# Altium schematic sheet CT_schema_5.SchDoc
size 235 x 258 mm
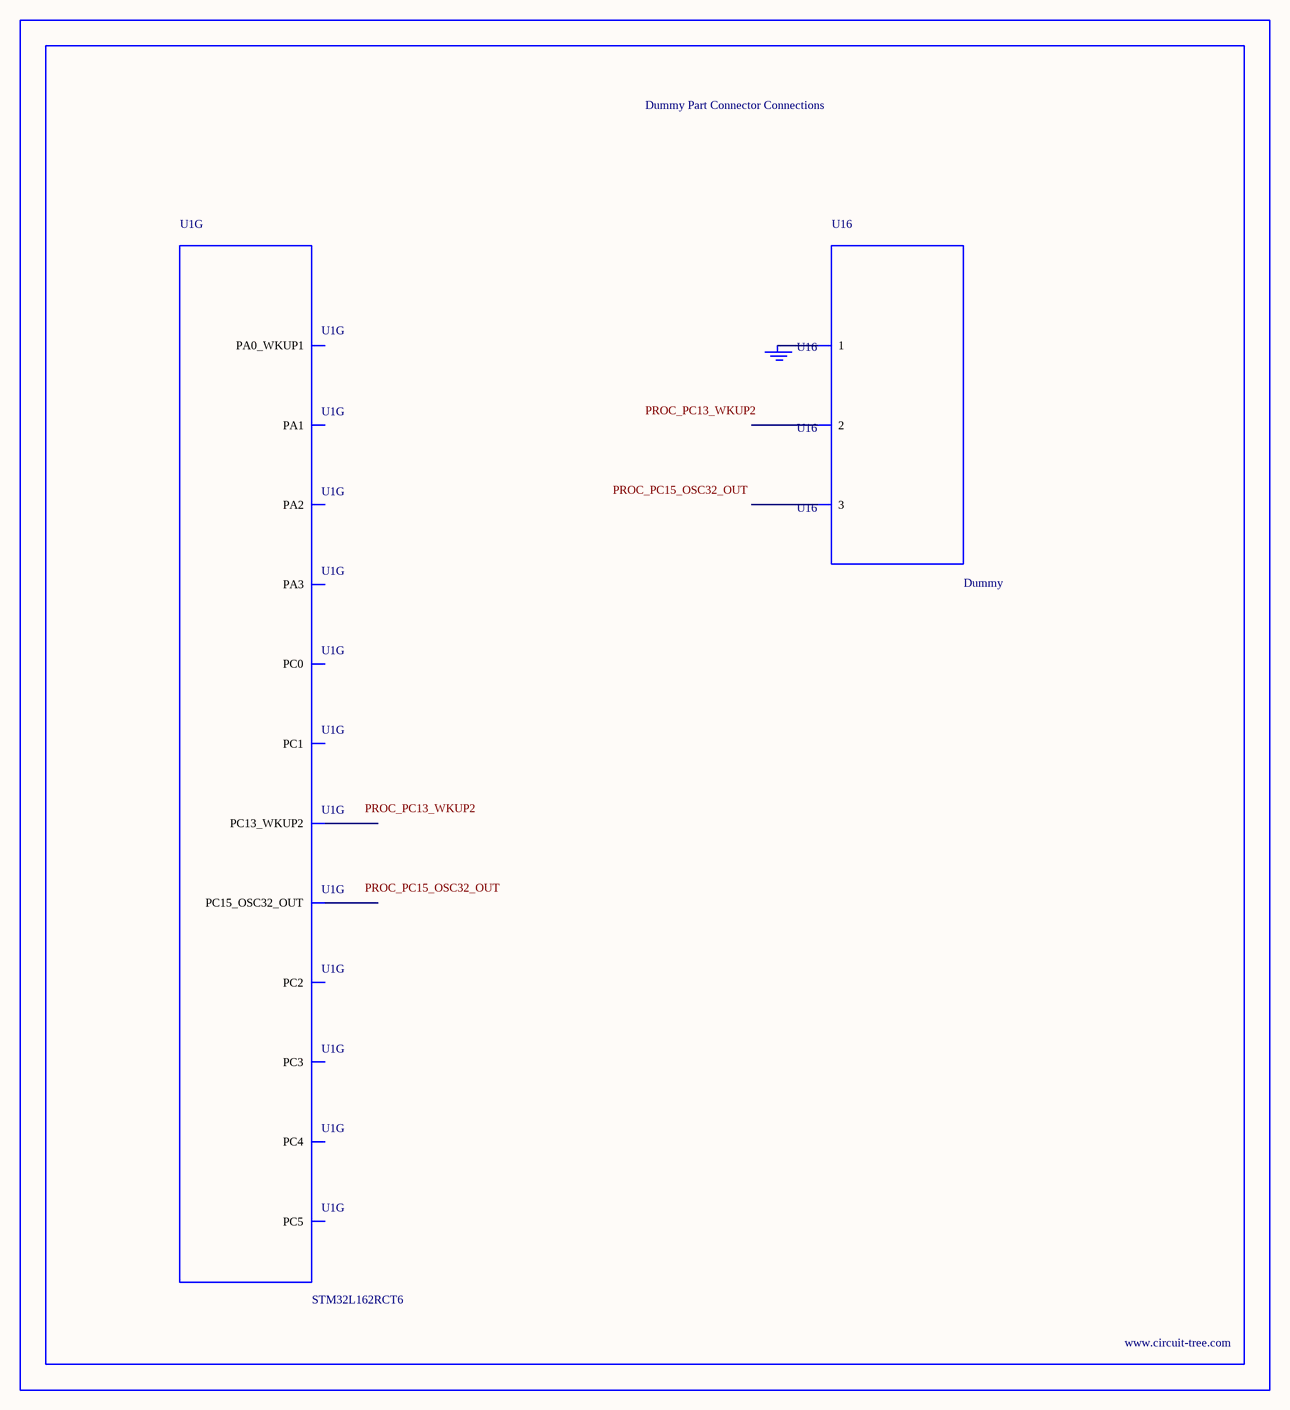
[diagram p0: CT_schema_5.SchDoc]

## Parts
BORDER4  (no value)
GND_INSTANCE_4_0  (no value)
U1  STM32L162RCT6  [LQFP64]  (part G of 7)
U16  Dummy  [DUMMY_PACKAGE_112]

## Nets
NetGND_INSTANCE_4_0_0: GND_INSTANCE_4_0.0(GND) U16.1

Not connected (* = marked no-connect by the designer): U1 2(PC13_WKUP2) 4(PC15_OSC32_OUT) 8(PC0) 9(PC1) 10(PC2) 11(PC3) 14(PA0_WKUP1) 15(PA1) 16(PA2) 17(PA3) 24(PC4) 25(PC5); U16 2 3

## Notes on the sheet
- Labels drawn without touching a wire or pin: PROC_PC13_WKUP2, PROC_PC15_OSC32_OUT

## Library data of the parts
BORDER4 = BORDER_PAGE4
GND_INSTANCE_4_0 = GND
